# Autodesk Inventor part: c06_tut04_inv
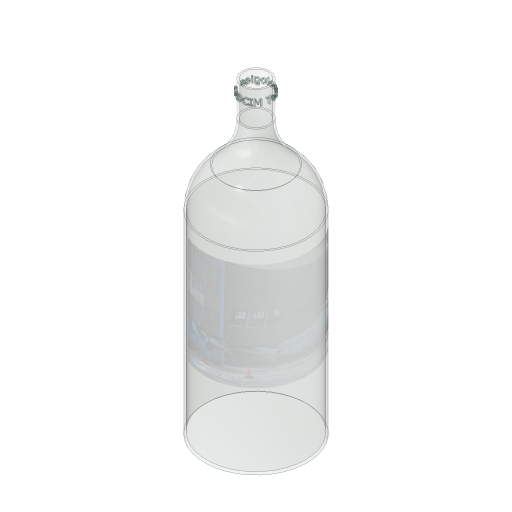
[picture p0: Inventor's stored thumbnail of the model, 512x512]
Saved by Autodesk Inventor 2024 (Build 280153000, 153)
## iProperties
Created: 2015-03
Part Number: c06_tut04_inv
Material: Glass
Document SubType Name: Modeling
Designer: Sandeep
Density: 2.18 g/cm^3
Appearance: Clear
Author: Sandeep
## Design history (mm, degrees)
sketch "Sketch1"
  geometry: L1 (8, 180)-(8, 160); L2 (30, 113.567)-(30, 0); L3 (30, 0)-(0, 0); L4 (0, 0)-(0, -98.027); L5 (7, 180)-(7, 160); L6 (29, 113.567)-(29, 1); L7 (29, 1)-(0, 1); L8 (8, 180)-(7, 180); L9 (0, 1)-(0, 0); A1 r 30 centre (38, 160) between (8, 160) and (19, 136.784); A2 r 30 centre (0, 113.567) between (30, 113.567) and (19, 136.784); A3 r 31 centre (38, 160) between (7, 160) and (18.367, 136.01); A4 r 29 centre (0, 113.567) between (29, 113.567) and (18.367, 136.01)
  constraints: 18 end point, 8 point on circle, 4 centre point, 3 perpendicular, 3 tangent, 2 parallel, 2 vertical, 1 horizontal, 4 other
  dimensions: "d0" = 20 distance of L1.start L1.end; "d1" = 30 radius of A1; "d2" = 30 radius of A2; "d7" = 180 vertical distance of L3.end L1.start; "d17" = 1 distance between parallel lines of L5 L1; "d18" = 60 diameter of L2 L4; "d19" = 16 diameter of L1 L4
revolve "Revolution1" sketch "Sketch1" stored, may be unused: angle "d9" = 90 deg
workplane "Work Plane1"
sketch "Sketch2"
  geometry: L1 (-21.117, 118.431)-(137.947, 118.431); L2 (137.947, 118.431)-(137.947, 105.984); L3 (137.947, 105.984)-(-21.117, 105.984); L4 (-21.117, 105.984)-(-21.117, 118.431); 1 further point
  constraints: 2 other
emboss "Emboss1" sketch "Sketch2" dims "d1" = 30, "d10" = 1, "d11" = 0
sketch "Sketch3"
  geometry: L1 (-60.338, 49.443)-(58.204, 49.443); L2 (58.204, 49.443)-(58.204, -13.263); L3 (58.204, -13.263)-(-60.338, -13.263); L4 (-60.338, -13.263)-(-60.338, 49.443); 1 further point; 1 other entity
  constraints: 2 other
feature "Decal1" sketch "Sketch3"
body "Solid1"
node "Image1"
